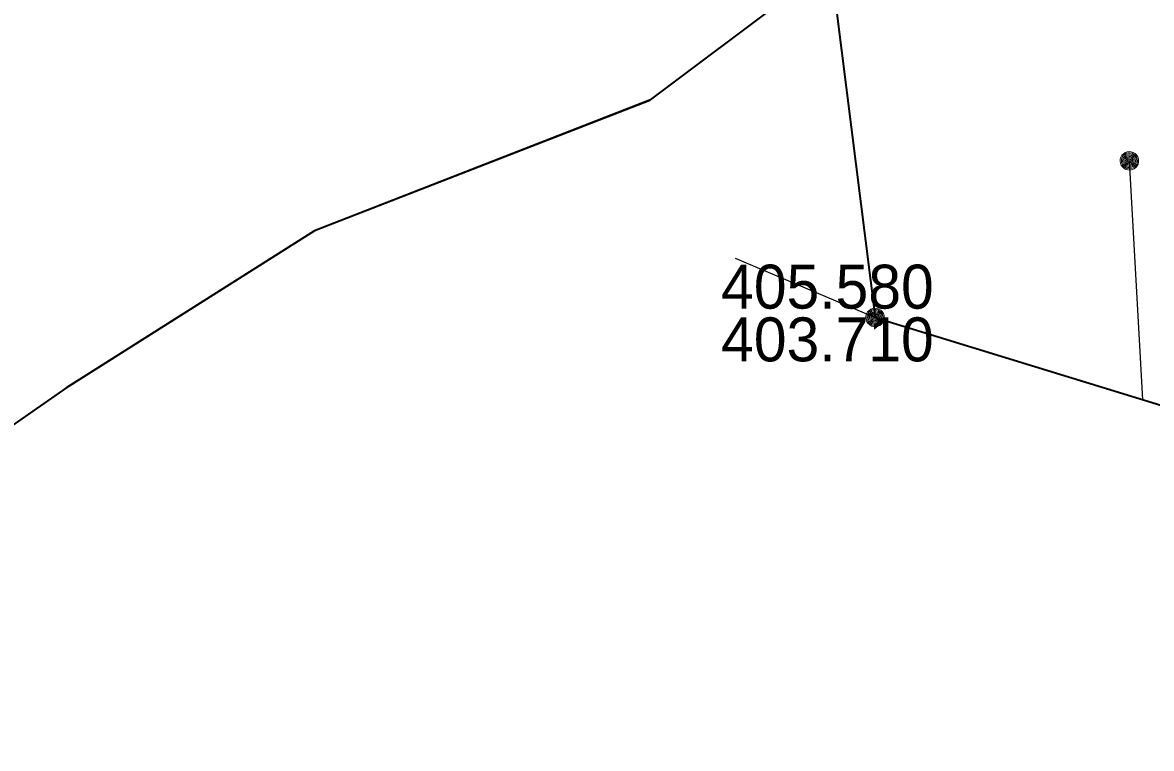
# Model space of a CAD drawing. Extents: x -873619 to -867639, y -1015082 to -1012326.
# Drawn here: x -868108.69 to -868080.46, y -1012849.97 to -1012831.8 of the extents above; entities that cross this region are included whole.
import ezdxf

# ---------------------------------------------------------------- set-up
doc = ezdxf.new("R2010")
doc.units = 0
doc.header["$LTSCALE"] = 0.44
for name, color, linetype, lineweight in [('1', 7, 'Continuous', 13), ('21', 7, 'Continuous', 35), ('23', 7, 'Continuous', 25), ('32', 7, 'Continuous', 13)]:
    doc.layers.add(name, color=color, linetype=linetype, lineweight=lineweight)

msp = doc.modelspace()

# ---------------------------------------------------------------- linework, layer by layer
at = {"layer": '1', "lineweight": 35}
for p, q in [((-868092.986, -1012833.731), (-868085.171, -1012827.86)), ((-868107.61, -1012840.95), (-868113.62, -1012845.13))]:
    msp.add_line(p, q, dxfattribs=at)
for points in [[(-868092.986, -1012833.731), (-868101.389, -1012837.01), (-868107.61, -1012840.95)], [(-868093, -1012833.748), (-868101.39, -1012837.01), (-868107.58, -1012840.931), (-868113.62, -1012845.13), (-868123.8, -1012852.73), (-868130.75, -1012859.04), (-868135.78, -1012863.43), (-868135.449, -1012863.638)]]:
    msp.add_lwpolyline(points, dxfattribs=at)
at = {"layer": '21'}
msp.add_lwpolyline([(-868134.19, -1012752.63), (-868112.27, -1012769.62), (-868107.42, -1012773.25), (-868101.75, -1012777.58), (-868093.15, -1012793.25), (-868087.37, -1012839.18), (-868062.459, -1012846.83), (-868020.28, -1012856.9)], dxfattribs=at)
at = {"layer": '23'}
for p, q in [((-868080.678, -1012841.235), (-868081.01, -1012835.26)), ((-868090.87, -1012837.7), (-868087.37, -1012839.18))]:
    msp.add_line(p, q, dxfattribs=at)
at = {"layer": '32'}
for points in [[(-868080.78, -1012835.259), (-868080.786, -1012835.207), (-868080.803, -1012835.157), (-868080.832, -1012835.113), (-868080.869, -1012835.076), (-868080.914, -1012835.049), (-868080.964, -1012835.032), (-868081.017, -1012835.028), (-868081.069, -1012835.035), (-868081.118, -1012835.054), (-868081.161, -1012835.083), (-868081.197, -1012835.122), (-868081.223, -1012835.167), (-868081.239, -1012835.218), (-868081.242, -1012835.27), (-868081.234, -1012835.322), (-868081.214, -1012835.371), (-868081.183, -1012835.414), (-868081.144, -1012835.448), (-868081.098, -1012835.474), (-868081.047, -1012835.488), (-868080.994, -1012835.49), (-868080.943, -1012835.48), (-868080.895, -1012835.459), (-868080.852, -1012835.428), (-868080.818, -1012835.387), (-868080.794, -1012835.341), (-868080.782, -1012835.29)], [(-868080.81, -1012835.259), (-868080.816, -1012835.21), (-868080.833, -1012835.164), (-868080.861, -1012835.124), (-868080.898, -1012835.092), (-868080.942, -1012835.07), (-868080.99, -1012835.059), (-868081.039, -1012835.059), (-868081.086, -1012835.072), (-868081.129, -1012835.096), (-868081.165, -1012835.129), (-868081.192, -1012835.17), (-868081.208, -1012835.217), (-868081.212, -1012835.266), (-868081.205, -1012835.314), (-868081.186, -1012835.359), (-868081.156, -1012835.399), (-868081.118, -1012835.43), (-868081.074, -1012835.45), (-868081.026, -1012835.46), (-868080.977, -1012835.458), (-868080.93, -1012835.443), (-868080.887, -1012835.418), (-868080.853, -1012835.384), (-868080.827, -1012835.342), (-868080.813, -1012835.295)], [(-868080.84, -1012835.259), (-868080.846, -1012835.214), (-868080.863, -1012835.172), (-868080.891, -1012835.137), (-868080.927, -1012835.11), (-868080.969, -1012835.093), (-868081.014, -1012835.088), (-868081.059, -1012835.094), (-868081.1, -1012835.113), (-868081.135, -1012835.141), (-868081.162, -1012835.178), (-868081.178, -1012835.22), (-868081.182, -1012835.265), (-868081.175, -1012835.31), (-868081.156, -1012835.351), (-868081.127, -1012835.385), (-868081.09, -1012835.411), (-868081.047, -1012835.427), (-868081.002, -1012835.43), (-868080.957, -1012835.422), (-868080.917, -1012835.402), (-868080.883, -1012835.373), (-868080.857, -1012835.335), (-868080.843, -1012835.292)], [(-868080.87, -1012835.259), (-868080.875, -1012835.218), (-868080.893, -1012835.181), (-868080.92, -1012835.15), (-868080.955, -1012835.129), (-868080.995, -1012835.118), (-868081.036, -1012835.12), (-868081.075, -1012835.133), (-868081.109, -1012835.157), (-868081.134, -1012835.189), (-868081.149, -1012835.227), (-868081.152, -1012835.268), (-868081.144, -1012835.308), (-868081.124, -1012835.344), (-868081.095, -1012835.373), (-868081.058, -1012835.392), (-868081.018, -1012835.4), (-868080.977, -1012835.396), (-868080.939, -1012835.381), (-868080.907, -1012835.355), (-868080.884, -1012835.321), (-868080.871, -1012835.282)], [(-868080.9, -1012835.259), (-868080.905, -1012835.223), (-868080.923, -1012835.191), (-868080.949, -1012835.166), (-868080.983, -1012835.151), (-868081.019, -1012835.148), (-868081.054, -1012835.156), (-868081.085, -1012835.176), (-868081.108, -1012835.204), (-868081.121, -1012835.238), (-868081.121, -1012835.275), (-868081.11, -1012835.31), (-868081.089, -1012835.339), (-868081.059, -1012835.36), (-868081.024, -1012835.37), (-868080.987, -1012835.368), (-868080.953, -1012835.354), (-868080.926, -1012835.331), (-868080.907, -1012835.299), (-868080.9, -1012835.264)], [(-868080.93, -1012835.259), (-868080.935, -1012835.228), (-868080.952, -1012835.202), (-868080.978, -1012835.185), (-868081.008, -1012835.178), (-868081.039, -1012835.182), (-868081.066, -1012835.199), (-868081.084, -1012835.223), (-868081.092, -1012835.254), (-868081.088, -1012835.284), (-868081.073, -1012835.312), (-868081.049, -1012835.331), (-868081.019, -1012835.34), (-868080.988, -1012835.337), (-868080.96, -1012835.323), (-868080.94, -1012835.299), (-868080.93, -1012835.27)], [(-868080.96, -1012835.259), (-868080.965, -1012835.235), (-868080.982, -1012835.217), (-868081.005, -1012835.208), (-868081.029, -1012835.211), (-868081.05, -1012835.225), (-868081.061, -1012835.247), (-868081.061, -1012835.272), (-868081.049, -1012835.293), (-868081.029, -1012835.307), (-868081.004, -1012835.31), (-868080.981, -1012835.301), (-868080.965, -1012835.283)], [(-868080.99, -1012835.259), (-868080.995, -1012835.244), (-868081.01, -1012835.238), (-868081.025, -1012835.242), (-868081.032, -1012835.256), (-868081.028, -1012835.271), (-868081.015, -1012835.28), (-868081, -1012835.277), (-868080.99, -1012835.265)], [(-868087.14, -1012839.179), (-868087.146, -1012839.127), (-868087.163, -1012839.077), (-868087.192, -1012839.033), (-868087.229, -1012838.996), (-868087.274, -1012838.969), (-868087.324, -1012838.952), (-868087.377, -1012838.948), (-868087.429, -1012838.955), (-868087.478, -1012838.974), (-868087.521, -1012839.003), (-868087.557, -1012839.042), (-868087.583, -1012839.087), (-868087.599, -1012839.138), (-868087.602, -1012839.19), (-868087.594, -1012839.242), (-868087.574, -1012839.291), (-868087.543, -1012839.334), (-868087.504, -1012839.368), (-868087.458, -1012839.394), (-868087.407, -1012839.408), (-868087.354, -1012839.41), (-868087.303, -1012839.4), (-868087.255, -1012839.379), (-868087.212, -1012839.348), (-868087.178, -1012839.307), (-868087.154, -1012839.261), (-868087.142, -1012839.21)], [(-868087.17, -1012839.179), (-868087.176, -1012839.13), (-868087.193, -1012839.084), (-868087.221, -1012839.044), (-868087.258, -1012839.012), (-868087.302, -1012838.99), (-868087.35, -1012838.979), (-868087.399, -1012838.979), (-868087.446, -1012838.992), (-868087.489, -1012839.016), (-868087.525, -1012839.049), (-868087.552, -1012839.09), (-868087.568, -1012839.137), (-868087.572, -1012839.186), (-868087.565, -1012839.234), (-868087.546, -1012839.279), (-868087.516, -1012839.319), (-868087.478, -1012839.35), (-868087.434, -1012839.37), (-868087.386, -1012839.38), (-868087.337, -1012839.378), (-868087.29, -1012839.363), (-868087.247, -1012839.338), (-868087.213, -1012839.304), (-868087.187, -1012839.262), (-868087.173, -1012839.215)], [(-868087.2, -1012839.179), (-868087.206, -1012839.134), (-868087.223, -1012839.092), (-868087.251, -1012839.057), (-868087.287, -1012839.03), (-868087.329, -1012839.013), (-868087.374, -1012839.008), (-868087.419, -1012839.014), (-868087.46, -1012839.033), (-868087.495, -1012839.061), (-868087.522, -1012839.098), (-868087.538, -1012839.14), (-868087.542, -1012839.185), (-868087.535, -1012839.23), (-868087.516, -1012839.271), (-868087.487, -1012839.305), (-868087.45, -1012839.331), (-868087.407, -1012839.347), (-868087.362, -1012839.35), (-868087.317, -1012839.342), (-868087.277, -1012839.322), (-868087.243, -1012839.293), (-868087.217, -1012839.255), (-868087.203, -1012839.212)], [(-868087.23, -1012839.179), (-868087.235, -1012839.138), (-868087.253, -1012839.101), (-868087.28, -1012839.07), (-868087.315, -1012839.049), (-868087.355, -1012839.038), (-868087.396, -1012839.04), (-868087.435, -1012839.053), (-868087.469, -1012839.077), (-868087.494, -1012839.109), (-868087.509, -1012839.147), (-868087.512, -1012839.188), (-868087.504, -1012839.228), (-868087.484, -1012839.264), (-868087.455, -1012839.293), (-868087.418, -1012839.312), (-868087.378, -1012839.32), (-868087.337, -1012839.316), (-868087.299, -1012839.301), (-868087.267, -1012839.275), (-868087.244, -1012839.241), (-868087.231, -1012839.202)], [(-868087.26, -1012839.179), (-868087.265, -1012839.143), (-868087.283, -1012839.111), (-868087.309, -1012839.086), (-868087.343, -1012839.071), (-868087.379, -1012839.068), (-868087.414, -1012839.076), (-868087.445, -1012839.096), (-868087.468, -1012839.124), (-868087.481, -1012839.158), (-868087.481, -1012839.195), (-868087.47, -1012839.23), (-868087.449, -1012839.259), (-868087.419, -1012839.28), (-868087.384, -1012839.29), (-868087.347, -1012839.288), (-868087.313, -1012839.274), (-868087.286, -1012839.251), (-868087.267, -1012839.219), (-868087.26, -1012839.184)], [(-868087.29, -1012839.179), (-868087.295, -1012839.148), (-868087.312, -1012839.122), (-868087.338, -1012839.105), (-868087.368, -1012839.098), (-868087.399, -1012839.102), (-868087.426, -1012839.119), (-868087.444, -1012839.143), (-868087.452, -1012839.174), (-868087.448, -1012839.204), (-868087.433, -1012839.232), (-868087.409, -1012839.251), (-868087.379, -1012839.26), (-868087.348, -1012839.257), (-868087.32, -1012839.243), (-868087.3, -1012839.219), (-868087.29, -1012839.19)], [(-868087.32, -1012839.179), (-868087.325, -1012839.155), (-868087.342, -1012839.137), (-868087.365, -1012839.128), (-868087.389, -1012839.131), (-868087.41, -1012839.145), (-868087.421, -1012839.167), (-868087.421, -1012839.192), (-868087.409, -1012839.213), (-868087.389, -1012839.227), (-868087.364, -1012839.23), (-868087.341, -1012839.221), (-868087.325, -1012839.203)], [(-868087.35, -1012839.179), (-868087.355, -1012839.164), (-868087.37, -1012839.158), (-868087.385, -1012839.162), (-868087.392, -1012839.176), (-868087.388, -1012839.191), (-868087.375, -1012839.2), (-868087.36, -1012839.197), (-868087.35, -1012839.185)]]:
    msp.add_lwpolyline(points, close=True, dxfattribs=at)

# ---------------------------------------------------------------- texts
at = {"layer": '1'}
for s, p in [('405.580 ', (-868091.221, -1012838.959)), ('403.710 ', (-868091.221, -1012840.279))]:
    msp.add_text(s, height=1.1, dxfattribs=at).set_placement(p)

doc.saveas('drawing.dxf')
